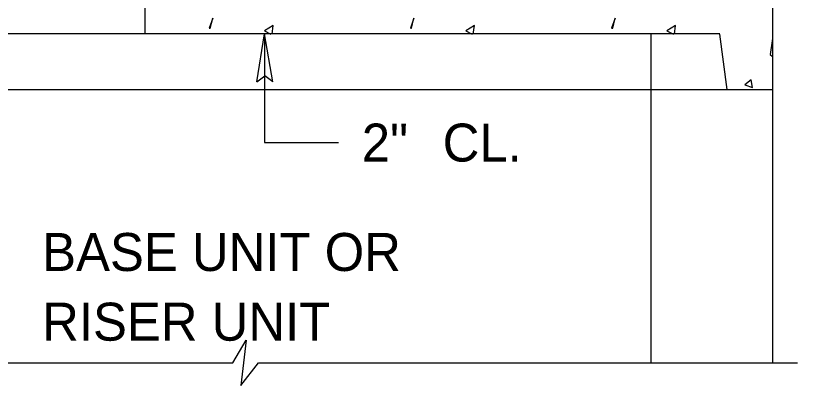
# Model space of a CAD drawing. Extents: x 1.8 to 9.1, y -6 to 4.
# Drawn here: x 7.631 to 8.864, y 0.596 to 1.18 of the extents above; entities that cross this region are included whole.
import ezdxf

# ---------------------------------------------------------------- set-up
doc = ezdxf.new("R2010")
doc.units = 0
for name, color, linetype in [('DETL-DIMS', 7, 'Continuous'), ('DETL-LINE', 7, 'Continuous'), ('DETL-NOTE', 7, 'Continuous'), ('DETL-PATT', 7, 'Continuous')]:
    doc.layers.add(name, color=color, linetype=linetype)

msp = doc.modelspace()

# ---------------------------------------------------------------- linework, layer by layer
at = {"layer": 'DETL-DIMS'}
for p, q in [((8.0114, 1.0752), (8.0233, 1.1508)), ((8.0365, 1.0754), (8.0233, 1.1508)), ((8.0233, 1.1508), (8.0233, 0.9793)), ((8.0114, 1.0752), (8.0239, 1.0848)), ((8.0365, 1.0754), (8.0239, 1.0848)), ((8.0233, 0.9793), (8.1401, 0.9793))]:
    msp.add_line(p, q, dxfattribs=at)
at = {"layer": 'DETL-LINE'}
for p, q in [((7.8344, 1.4528), (7.8344, 1.1508)), ((8.8245, 1.3149), (8.8245, 0.6318)), ((8.7417, 1.1508), (7.2358, 1.1508)), ((8.6327, 1.1508), (8.6327, 0.6318)), ((8.753, 1.0629), (8.7417, 1.1506)), ((7.2246, 1.0629), (8.753, 1.0629)), ((8.753, 1.0629), (8.8245, 1.0629)), ((7.9731, 0.6318), (7.9945, 0.6675)), ((7.9945, 0.6675), (7.986, 0.596)), ((7.1167, 0.6318), (7.9731, 0.6318)), ((7.986, 0.596), (8.0139, 0.6318)), ((8.0139, 0.6318), (8.8639, 0.6318))]:
    msp.add_line(p, q, dxfattribs=at)
at = {"layer": 'DETL-PATT'}
for points in [[(7.9359, 1.1597), (7.9378, 1.1597), (7.9416, 1.1757)], [(8.2534, 1.1597), (8.2552, 1.1597), (8.259, 1.1757)], [(8.5708, 1.1597), (8.5727, 1.1597), (8.5764, 1.1757)], [(8.7911, 1.0785), (8.7812, 1.0705), (8.7929, 1.0663)]]:
    msp.add_lwpolyline(points, close=True, dxfattribs=at)
for points in [[(8.0351, 1.1506), (8.0369, 1.1639), (8.0232, 1.1559), (8.0334, 1.1506)], [(8.3525, 1.1506), (8.3543, 1.1639), (8.3406, 1.1559), (8.3508, 1.1506)], [(8.67, 1.1506), (8.6717, 1.1639), (8.658, 1.1559), (8.6682, 1.1506)], [(8.8245, 1.1436), (8.8245, 1.1436), (8.8208, 1.1182), (8.8245, 1.1154)]]:
    msp.add_lwpolyline(points, dxfattribs=at)

# ---------------------------------------------------------------- texts
at = {"layer": 'DETL-NOTE'}
for s, p in [('2"', (8.1767, 0.9493)), ('CL.', (8.3043, 0.9493)), ('BASE UNIT OR', (7.6725, 0.7766)), ('RISER UNIT', (7.6725, 0.6666))]:
    msp.add_text(s, height=0.05998, dxfattribs=at).set_placement(p)

doc.saveas('drawing.dxf')
